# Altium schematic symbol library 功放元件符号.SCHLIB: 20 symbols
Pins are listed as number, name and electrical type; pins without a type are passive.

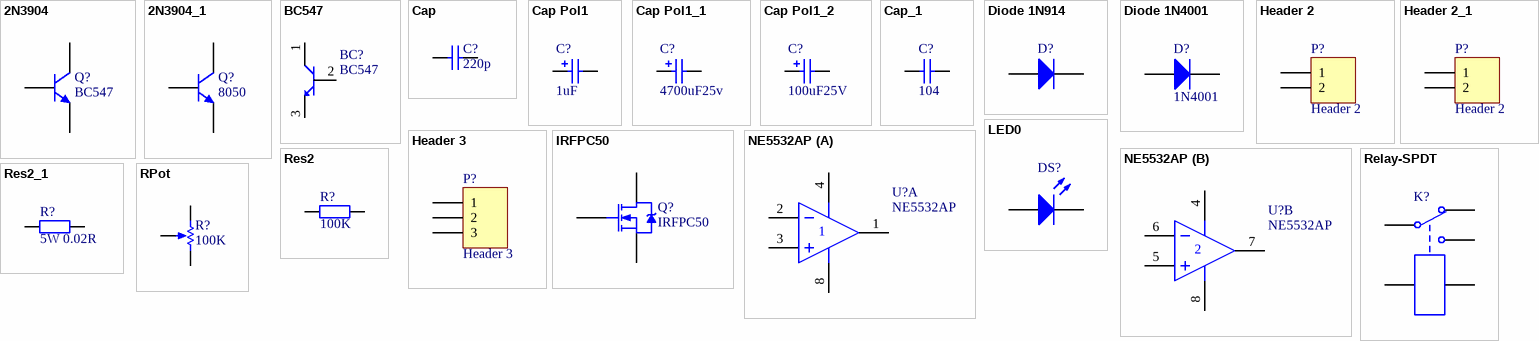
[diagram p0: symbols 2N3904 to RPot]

## 2N3904
designator Q?, comment BC547
NPN General Purpose Amplifier
footprint BCY-W3/E4
simulation model 2N3904 (NPN)
signal-integrity model 2N3904
pins: 1 C, 2 B, 3 E

## 2N3904_1
designator Q?, comment 8050
NPN General Purpose Amplifier
footprint BCY-W3/E4
simulation model 2N3904 (NPN)
signal-integrity model 2N3904
pins: 1 E, 2 B, 3 C

## BC547
designator BC?
pins: 1, 2, 3

## Cap
designator C?  value 220p  (hidden comment: Cap)
Capacitor
footprint AXIAL-0.4
footprint CAPR2.54-5.1x3.2 (Capacitor, Ceramic, Thru-Hole, Dipped Radial; Body 5.1 x 3.2 mm (WxT) Pin Spacing 2.54 mm (typ))
footprint CAPR5.08-7.8x3.2 (Capacitor, Ceramic, Thru-Hole, Dipped Radial; Body 7.8 x 3.2 mm (WxT) Pin Spacing 5.08 mm (typ))
simulation model CAP (Capacitor)
signal-integrity model Cap
pins: 1, 2

## Cap Pol1
designator C?  value 1uF  (hidden comment: Cap Pol1)
Polarized Capacitor (Radial)
footprint CAPPR2-5x6.8
footprint CAPPR1.27-1.7x2.8 (Capacitor, Radial, Tantalum; Body 1.7 x 2.8 mm (Dia.xH max); Pin Spacing 1.27 mm (typ))
footprint CAPPR1.5-4x5 (Capacitor, Electrolytic, Radial; Body 4 x 5 mm (Dia.xH typ); Pin Spacing 1.5 mm (typ))
footprint CAPPR2-5x6.8 (Capacitor, Electrolytic, Radial; Body 5 x 6.8 mm (Dia.xH typ); Pin Spacing 2 mm (typ))
footprint CAPPR5-5x5 (Capacitor, Electrolytic, Radial; Body 5 x 5 mm (Dia.xH typ); Pin Spacing 5 mm (typ))
footprint CAPPR7.5-16x35 (Capacitor, Electrolytic, Radial; Body 16 x 35 mm (Dia.xH typ); Pin Spacing 7.5 mm (typ))
simulation model CAP (Capacitor)
signal-integrity model Cap Pol
pins: 1, 2
1 alternate drawing of the same symbol

## Cap Pol1_1
designator C?, comment value 4700uF25v  (hidden comment: Cap Pol1)
Polarized Capacitor (Radial)
footprint RB7.6-15
footprint CAPPR1.27-1.7x2.8 (Capacitor, Radial, Tantalum; Body 1.7 x 2.8 mm (Dia.xH max); Pin Spacing 1.27 mm (typ))
footprint CAPPR1.5-4x5 (Capacitor, Electrolytic, Radial; Body 4 x 5 mm (Dia.xH typ); Pin Spacing 1.5 mm (typ))
footprint CAPPR2-5x6.8 (Capacitor, Electrolytic, Radial; Body 5 x 6.8 mm (Dia.xH typ); Pin Spacing 2 mm (typ))
footprint CAPPR5-5x5 (Capacitor, Electrolytic, Radial; Body 5 x 5 mm (Dia.xH typ); Pin Spacing 5 mm (typ))
footprint CAPPR7.5-16x35 (Capacitor, Electrolytic, Radial; Body 16 x 35 mm (Dia.xH typ); Pin Spacing 7.5 mm (typ))
simulation model CAP (Capacitor)
signal-integrity model Cap Pol
pins: 1, 2
1 alternate drawing of the same symbol

## Cap Pol1_2
designator C?, comment value 100uF25V  (hidden comment: Cap Pol1)
Polarized Capacitor (Radial)
footprint CAPPR2-5x6.8
footprint CAPPR1.27-1.7x2.8 (Capacitor, Radial, Tantalum; Body 1.7 x 2.8 mm (Dia.xH max); Pin Spacing 1.27 mm (typ))
footprint CAPPR1.5-4x5 (Capacitor, Electrolytic, Radial; Body 4 x 5 mm (Dia.xH typ); Pin Spacing 1.5 mm (typ))
footprint CAPPR2-5x6.8 (Capacitor, Electrolytic, Radial; Body 5 x 6.8 mm (Dia.xH typ); Pin Spacing 2 mm (typ))
footprint CAPPR5-5x5 (Capacitor, Electrolytic, Radial; Body 5 x 5 mm (Dia.xH typ); Pin Spacing 5 mm (typ))
footprint CAPPR7.5-16x35 (Capacitor, Electrolytic, Radial; Body 16 x 35 mm (Dia.xH typ); Pin Spacing 7.5 mm (typ))
simulation model CAP (Capacitor)
signal-integrity model Cap Pol
pins: 1, 2
1 alternate drawing of the same symbol

## Cap_1
designator C?, comment value 104  (hidden comment: Cap)
Capacitor
footprint CAPR2.54-5.1x3.2
footprint CAPR2.54-5.1x3.2 (Capacitor, Ceramic, Thru-Hole, Dipped Radial; Body 5.1 x 3.2 mm (WxT) Pin Spacing 2.54 mm (typ))
footprint CAPR5.08-7.8x3.2 (Capacitor, Ceramic, Thru-Hole, Dipped Radial; Body 7.8 x 3.2 mm (WxT) Pin Spacing 5.08 mm (typ))
simulation model CAP (Capacitor)
signal-integrity model Cap
footprint CAPR5-4X5
pins: 1, 2

## Diode 1N914
designator D?  (value not drawn)
High Conductance Fast Diode
footprint DIO7.1-3.9x1.9 (Diode, Axial; Body 3.8 x 1.9 mm (LxDia. max), Lead Dia. 0.53 mm (max))
simulation model 1N914 (DIODE)
signal-integrity model 1N914
pins: 1 A, 2 K

## Diode 1N4001
designator D?, comment 1N4001
1 Amp General Purpose Rectifier
footprint DIO10.46-5.3x2.8
simulation model 1N4001 (DIODE)
signal-integrity model 1N4001
pins: 1 A, 2 K

## Header 2
designator P?
Header, 2-Pin
footprint 音频线
signal-integrity model Connector
pins: 1, 2

## Header 2_1
designator P?, comment Header 2
Header, 2-Pin
footprint pcZOU
signal-integrity model Connector
pins: 1, 2

## Header 3
designator P?
Header, 3-Pin
footprint duanzi
signal-integrity model Connector
pins: 1, 2, 3

## IRFPC50
designator Q?
HEXFET Power MOSFET; Note: Pin 2 is electrically connected to the Heatsink (4).
footprint TO-247AC
pins: 1 G, 2 D, 3 S

## LED0
designator DS?  (value not drawn)
Typical INFRARED GaAs LED
footprint CAPPR2-5x6.8
simulation model LED0 (Diode)
footprint CAPPR1.5-4x5
pins: 1 A, 2 K

## NE5532AP
designator U?
Dual Low-Noise Operational Amplifier
footprint P008
pins on every part: 4 v-, 8 V+
part A pins: 1 OUT, 2 IN-, 3 IN+
part B pins: 5 IN+, 6 IN-, 7 OUT

## Relay-SPDT
designator K?  (value not drawn)
Single-Pole Dual-Throw Relay
footprint jidianqi
simulation model SPDTRELAY (Spice Subcircuit)
pins: 1, 2, 3, 4, 5

## Res2
designator R?  value 100K  (hidden comment: Res2)
Resistor
footprint AXIAL-0.4
simulation model RESISTOR (Resistor)
signal-integrity model Res
pins: 1, 2

## Res2_1
designator R?, comment value 5W 0.02R  (hidden comment: Res2)
Resistor
footprint 0.02r   5W
simulation model RESISTOR (Resistor)
signal-integrity model Res
pins: 1, 2

## RPot
designator R?  value 100K
Potentiometer; Sim Note: Enter the Resistance value and the set point into parameter fields.; Set Position: 0.5
footprint 电位器
simulation model POT (Potentiometer)
pins: 1 TOP, 2 TAP, 3 BOT
1 alternate drawing of the same symbol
